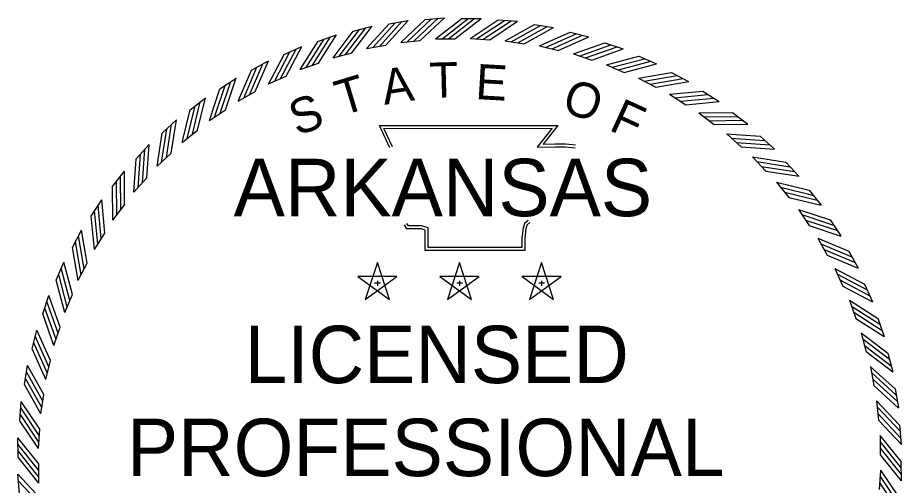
# Model space of a CAD drawing. Extents: x 3046 to 131673, y -8885 to 10756.
# Drawn here: x 3046.5 to 3294.9, y 440.1 to 571.6 of the extents above; entities that cross this region are included whole.
import ezdxf

# ---------------------------------------------------------------- set-up
doc = ezdxf.new("R2010")
doc.units = 0
doc.layers.add('STAMP_PP', color=7, linetype='Continuous')

msp = doc.modelspace()

# ---------------------------------------------------------------- linework, layer by layer
at = {"layer": 'STAMP_PP'}
for p, q in [((3161.08, 571.13), (3166.5, 571.63)), ((3171.39, 571.43), (3176.83, 571.43)), ((3140.85, 567.86), (3146.11, 569.24)), ((3150.9, 569.91), (3156.26, 570.86)), ((3181.58, 571.02), (3187, 570.63)), ((3191.75, 569.7), (3197.12, 568.86)), ((3131.01, 564.98), (3136.14, 566.8)), ((3201.77, 567.55), (3207.06, 566.26)), ((3154.22, 564.68), (3159.65, 565.18)), ((3163.96, 565.64), (3169.41, 565.64)), ((3173.75, 565.8), (3179.19, 565.4)), ((3183.51, 565.14), (3188.9, 564.29)), ((3211.59, 564.57), (3216.75, 562.85)), ((3121.43, 561.3), (3126.4, 563.53)), ((3135.14, 560.37), (3140.42, 561.76)), ((3144.59, 562.92), (3149.96, 563.87)), ((3193.19, 563.68), (3198.49, 562.39)), ((3112.2, 556.85), (3116.96, 559.48)), ((3202.71, 561.42), (3207.89, 559.7)), ((3221.12, 560.8), (3226.13, 558.66)), ((3125.94, 557.05), (3131.08, 558.87)), ((3212.02, 558.39), (3217.03, 556.25)), ((3103.36, 551.64), (3107.89, 554.66)), ((3117.04, 552.98), (3122.01, 555.21)), ((3221.04, 554.6), (3225.86, 552.05)), ((3230.31, 556.24), (3235.12, 553.7)), ((3094.98, 545.72), (3099.24, 549.11)), ((3108.5, 548.19), (3113.27, 550.83)), ((3229.72, 550.08), (3234.32, 547.14)), ((3239.1, 550.95), (3243.68, 548.02)), ((3100.39, 542.71), (3104.93, 545.73)), ((3238, 544.85), (3242.33, 541.54)), ((3247.41, 544.95), (3251.74, 541.64)), ((3087.12, 539.14), (3091.09, 542.86)), ((3092.76, 536.57), (3097.04, 539.96)), ((3245.82, 538.96), (3249.86, 535.3)), ((3255.21, 538.28), (3259.24, 534.63)), ((3079.83, 531.92), (3083.48, 535.96)), ((3085.67, 529.83), (3089.64, 533.56)), ((3253.12, 532.45), (3256.85, 528.47)), ((3262.42, 530.99), (3266.14, 527.02)), ((3073.17, 524.13), (3076.47, 528.45)), ((3079.15, 522.53), (3082.81, 526.58)), ((3259.86, 525.35), (3263.25, 521.08)), ((3269.01, 523.13), (3272.39, 518.87)), ((3067.16, 515.81), (3070.1, 520.39)), ((3073.26, 514.71), (3076.57, 519.05)), ((3265.99, 517.72), (3269.02, 513.18)), ((3274.93, 514.75), (3277.94, 510.23)), ((3061.87, 507.03), (3064.41, 511.84)), ((3068.04, 506.44), (3070.98, 511.03)), ((3271.47, 509.61), (3274.11, 504.84)), ((3280.13, 505.92), (3282.76, 501.15)), ((3057.32, 497.84), (3059.46, 502.84)), ((3063.51, 497.76), (3066.06, 502.58)), ((3147.61, 502.79), (3144.21, 492.34)), ((3151, 492.35), (3147.62, 502.8)), ((3170.69, 502.79), (3167.28, 492.34)), ((3174.08, 492.35), (3170.7, 502.8)), ((3193.77, 502.79), (3190.36, 492.34)), ((3197.16, 492.35), (3193.77, 502.8)), ((3276.26, 501.08), (3278.5, 496.1)), ((3153.1, 498.8), (3142.11, 498.81)), ((3142.12, 498.8), (3151, 492.33)), ((3144.22, 492.35), (3153.11, 498.8)), ((3146.83, 497.04), (3148.46, 497.04)), ((3147.62, 497.63), (3147.62, 496.25)), ((3176.18, 498.8), (3165.19, 498.81)), ((3165.2, 498.8), (3174.08, 492.33)), ((3167.3, 492.35), (3176.19, 498.8)), ((3169.91, 497.04), (3171.54, 497.04)), ((3170.7, 497.63), (3170.7, 496.25)), ((3199.25, 498.8), (3188.27, 498.81)), ((3188.28, 498.8), (3197.16, 492.33)), ((3190.37, 492.35), (3199.27, 498.8)), ((3192.98, 497.04), (3194.62, 497.04)), ((3193.78, 497.63), (3193.78, 496.25)), ((3284.59, 496.68), (3286.82, 491.72)), ((3053.54, 488.3), (3055.26, 493.47)), ((3059.72, 488.74), (3061.86, 493.75)), ((3280.33, 492.18), (3282.15, 487.03)), ((3288.27, 487.11), (3290.08, 481.98)), ((3056.69, 479.43), (3058.41, 484.6)), ((3050.56, 478.49), (3051.85, 483.78)), ((3283.66, 482.97), (3285.04, 477.69)), ((3291.14, 477.26), (3292.53, 472)), ((3054.43, 469.91), (3055.72, 475.2)), ((3048.41, 468.46), (3049.25, 473.84)), ((3286.21, 473.52), (3287.15, 468.15)), ((3293.2, 467.21), (3294.14, 461.86)), ((3052.97, 460.23), (3053.82, 465.61)), ((3047.09, 458.29), (3047.49, 463.72)), ((3287.97, 463.89), (3288.47, 458.46)), ((3052.32, 450.46), (3052.72, 455.9)), ((3294.41, 457.03), (3294.91, 451.61)), ((3046.61, 448.05), (3046.56, 453.49)), ((3288.93, 454.15), (3288.98, 448.7)), ((3052.47, 440.68), (3052.42, 446.13)), ((3294.79, 446.78), (3294.84, 441.34)), ((3046.98, 437.8), (3046.48, 443.22)), ((3289.08, 444.37), (3288.68, 438.93))]:
    msp.add_line(p, q, dxfattribs=at)
for points in [[(3157.84, 565.04), (3164.7, 571.48)], [(3159.64, 565.19), (3166.5, 571.63)], [(3163.95, 565.64), (3171.38, 571.43)], [(3165.71, 565.62), (3173.13, 571.41)], [(3167.6, 565.66), (3175.02, 571.45)], [(3169.41, 565.65), (3176.83, 571.44)], [(3140.41, 561.76), (3146.12, 569.25)], [(3144.59, 562.92), (3150.89, 569.91)], [(3146.31, 563.2), (3152.62, 570.19)], [(3148.17, 563.57), (3154.47, 570.56)], [(3149.96, 563.87), (3156.26, 570.86)], [(3154.21, 564.68), (3161.08, 571.12)], [(3155.96, 564.82), (3162.82, 571.27)], [(3173.74, 565.79), (3181.57, 571.02)], [(3175.49, 565.65), (3183.31, 570.88)], [(3177.37, 565.55), (3185.2, 570.78)], [(3179.18, 565.4), (3187.01, 570.63)], [(3183.51, 565.14), (3191.74, 569.7)], [(3185.23, 564.85), (3193.47, 569.41)], [(3187.11, 564.59), (3195.34, 569.16)], [(3131.07, 558.87), (3136.14, 566.8)], [(3135.14, 560.36), (3140.84, 567.85)], [(3136.84, 560.79), (3142.54, 568.28)], [(3138.65, 561.32), (3144.36, 568.8)], [(3188.89, 564.3), (3197.13, 568.86)], [(3193.18, 563.68), (3201.77, 567.55)], [(3194.88, 563.25), (3203.46, 567.12)], [(3196.73, 562.84), (3205.31, 566.71)], [(3125.93, 557.04), (3131, 564.98)], [(3127.59, 557.61), (3132.66, 565.54)], [(3129.36, 558.28), (3134.42, 566.21)], [(3198.48, 562.39), (3207.07, 566.26)], [(3202.71, 561.42), (3211.58, 564.57)], [(3204.36, 560.85), (3213.24, 564)], [(3118.64, 553.67), (3123.03, 562)], [(3120.34, 554.49), (3124.74, 562.81)], [(3122, 555.22), (3126.4, 563.54)], [(3206.17, 560.3), (3215.04, 563.44)], [(3207.88, 559.71), (3216.76, 562.85)], [(3113.27, 550.83), (3116.96, 559.49)], [(3117.03, 552.97), (3121.43, 561.3)], [(3212.01, 558.39), (3221.11, 560.79)], [(3213.62, 557.69), (3222.72, 560.09)], [(3215.37, 556.98), (3224.47, 559.39)], [(3108.5, 548.18), (3112.19, 556.84)], [(3110.04, 549.01), (3113.73, 557.67)], [(3111.67, 549.96), (3115.37, 558.62)], [(3217.03, 556.25), (3226.13, 558.66)], [(3104.92, 545.73), (3107.89, 554.67)], [(3221.04, 554.6), (3230.31, 556.24)], [(3222.58, 553.77), (3231.85, 555.41)], [(3224.27, 552.92), (3233.54, 554.56)], [(3100.39, 542.7), (3103.36, 551.63)], [(3101.86, 543.66), (3104.82, 552.59)], [(3103.41, 544.74), (3106.37, 553.67)], [(3225.86, 552.06), (3235.13, 553.7)], [(3097.03, 539.96), (3099.25, 549.11)], [(3229.71, 550.08), (3239.09, 550.95)], [(3231.18, 549.12), (3240.55, 549.99)], [(3094.14, 537.64), (3096.36, 546.79)], [(3095.6, 538.85), (3097.82, 548)], [(3232.8, 548.13), (3242.17, 549.01)], [(3234.31, 547.14), (3243.69, 548.02)], [(3092.76, 536.57), (3094.98, 545.72)], [(3237.99, 544.85), (3247.4, 544.95)], [(3088.3, 532.34), (3089.76, 541.64)], [(3089.64, 533.56), (3091.09, 542.86)], [(3239.37, 543.78), (3248.79, 543.87)], [(3240.9, 542.66), (3250.31, 542.76)], [(3242.33, 541.55), (3251.74, 541.64)], [(3085.67, 529.83), (3087.12, 539.13)], [(3086.95, 531.01), (3088.41, 540.31)], [(3151.11, 535.02), (3148.21, 541.3), (3198.39, 541.33), (3194.2, 536.06), (3197.61, 536.11), (3200.46, 536.14), (3203.3, 535.83)], [(3151.84, 535.35), (3149.46, 540.5), (3196.74, 540.53), (3192.54, 535.24), (3197.62, 535.31), (3200.42, 535.35), (3203.22, 535.04)], [(3245.81, 538.96), (3255.2, 538.28)], [(3247.1, 537.78), (3256.49, 537.09)], [(3081.57, 525.24), (3082.25, 534.63)], [(3082.8, 526.57), (3083.48, 535.96)], [(3248.53, 536.54), (3257.92, 535.86)], [(3249.86, 535.31), (3259.25, 534.63)], [(3079.15, 522.52), (3079.83, 531.91)], [(3080.34, 523.81), (3081.02, 533.2)], [(3253.11, 532.45), (3262.41, 530.99)], [(3254.3, 531.16), (3263.6, 529.7)], [(3255.62, 529.81), (3264.92, 528.35)], [(3075.45, 517.62), (3075.35, 527.03)], [(3076.56, 519.05), (3076.47, 528.46)], [(3256.85, 528.47), (3266.15, 527.02)], [(3074.34, 516.09), (3074.24, 525.5)], [(3259.85, 525.35), (3269, 523.13)], [(3073.26, 514.71), (3073.16, 524.12)], [(3260.93, 523.97), (3270.08, 521.75)], [(3262.13, 522.51), (3271.28, 520.3)], [(3070.97, 511.03), (3070.1, 520.4)], [(3263.25, 521.08), (3272.4, 518.87)], [(3068.99, 507.9), (3068.12, 517.27)], [(3069.98, 509.51), (3069.1, 518.88)], [(3265.98, 517.72), (3274.92, 514.76)], [(3068.04, 506.43), (3067.16, 515.8)], [(3189.98, 514.61), (3188.93, 513.75), (3188.56, 512.4), (3188.27, 509.7), (3188.27, 506.98), (3161.85, 506.98), (3161.85, 510.87), (3161.85, 512.49), (3160.03, 513.05), (3156.36, 513.05), (3155.89, 513.77)], [(3266.94, 516.26), (3275.88, 513.29)], [(3268.02, 514.71), (3276.96, 511.74)], [(3066.06, 502.57), (3064.41, 511.84)], [(3190.49, 513.99), (3189.63, 513.29), (3189.35, 512.25), (3189.06, 509.65), (3189.06, 506.18), (3161.05, 506.18), (3161.05, 510.87), (3161.05, 511.91), (3159.91, 512.25), (3155.93, 512.25), (3155.22, 513.33)], [(3269.02, 513.19), (3277.95, 510.22)], [(3065.19, 500.98), (3063.55, 510.25)], [(3271.46, 509.61), (3280.12, 505.92)], [(3063.51, 497.75), (3061.87, 507.02)], [(3064.35, 499.29), (3062.7, 508.56)], [(3272.3, 508.07), (3280.96, 504.38)], [(3273.25, 506.44), (3281.91, 502.75)], [(3274.11, 504.85), (3282.77, 501.15)], [(3061.86, 493.75), (3059.46, 502.85)], [(3060.43, 490.33), (3058.02, 499.43)], [(3061.13, 492.09), (3058.73, 501.19)], [(3276.26, 501.08), (3284.58, 496.68)], [(3276.96, 499.48), (3285.28, 495.08)], [(3059.72, 488.73), (3057.32, 497.83)], [(3277.77, 497.77), (3286.1, 493.37)], [(3278.5, 496.11), (3286.83, 491.71)], [(3058.4, 484.6), (3055.26, 493.47)], [(3280.33, 492.18), (3288.26, 487.11)], [(3057.26, 481.08), (3054.11, 489.95)], [(3057.82, 482.88), (3054.67, 491.76)], [(3280.9, 490.52), (3288.83, 485.46)], [(3056.69, 479.42), (3053.54, 488.29)], [(3281.57, 488.76), (3289.5, 483.69)], [(3282.15, 487.04), (3290.09, 481.97)], [(3055.27, 473.44), (3051.4, 482.02)], [(3055.72, 475.2), (3051.85, 483.78)], [(3283.65, 482.97), (3291.14, 477.27)], [(3054.87, 471.6), (3051, 480.18)], [(3284.08, 481.28), (3291.57, 475.57)], [(3054.44, 469.9), (3050.57, 478.48)], [(3284.6, 479.46), (3292.09, 473.75)], [(3285.05, 477.7), (3292.53, 472)], [(3053.52, 463.82), (3048.95, 472.05)], [(3053.82, 465.61), (3049.25, 473.84)], [(3286.2, 473.53), (3293.19, 467.22)], [(3053.26, 461.95), (3048.7, 470.18)], [(3286.49, 471.8), (3293.48, 465.49)], [(3286.86, 469.94), (3293.85, 463.64)], [(3052.98, 460.22), (3048.41, 468.45)], [(3287.16, 468.16), (3294.15, 461.85)], [(3052.71, 455.89), (3047.48, 463.72)], [(3287.96, 463.9), (3294.41, 457.04)], [(3288.11, 462.15), (3294.55, 455.29)], [(3052.47, 452.2), (3047.24, 460.03)], [(3052.56, 454.09), (3047.33, 461.92)], [(3288.32, 460.27), (3294.77, 453.41)], [(3052.32, 450.46), (3047.09, 458.28)], [(3288.47, 458.47), (3294.92, 451.61)], [(3052.41, 446.12), (3046.56, 453.49)], [(3288.92, 454.16), (3294.78, 446.79)], [(3288.92, 452.41), (3294.78, 445.04)], [(3052.41, 444.31), (3046.56, 451.68)], [(3052.47, 442.42), (3046.62, 449.79)], [(3288.98, 450.52), (3294.84, 443.15)], [(3052.47, 440.67), (3046.62, 448.04)], [(3288.98, 448.7), (3294.84, 441.33)], [(3052.93, 436.36), (3046.48, 443.22)], [(3288.93, 442.63), (3294.16, 434.8)], [(3289.08, 444.37), (3294.31, 436.54)], [(3053.08, 434.55), (3046.63, 441.41)], [(3288.83, 440.74), (3294.06, 432.91)]]:
    msp.add_lwpolyline(points, dxfattribs=at)

# ---------------------------------------------------------------- texts
for s, rotation, p in [('T', 1.4789, (3162.37, 549.07)), ('A', 8.6788, (3149.58, 547.1)), ('E', 356.672, (3175.03, 548.77)), ('T', 16.9015, (3137.57, 543.96)), ('O', 341.2218, (3199.07, 545.37)), ('S', 19.7726, (3124.98, 538.31)), ('F', 335.3628, (3212.41, 540.16))]:
    msp.add_text(s, height=9.9, rotation=rotation, dxfattribs=at).set_placement(p)
for s, height, p in [('ARKANSAS', 16.155, (3107.2, 515.79)), ('LICENSED', 16.155, (3110.27, 468.84)), ('PROFESSIONAL', 16.1547, (3077.19, 442.69))]:
    msp.add_text(s, height=height, dxfattribs=at).set_placement(p)

doc.saveas('drawing.dxf')
